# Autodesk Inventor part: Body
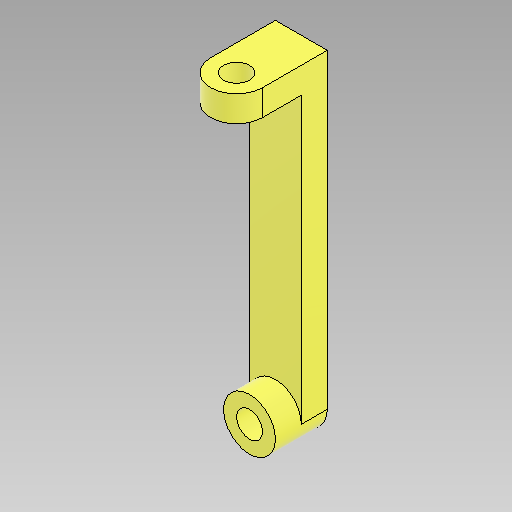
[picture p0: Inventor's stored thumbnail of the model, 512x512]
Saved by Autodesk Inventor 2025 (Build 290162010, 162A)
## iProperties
Created: 2024-10
Part Number: Body
Material: Generic
Document SubType Name: Modeling
Designer: Dennis
Mass: 31.7124 g
Surface Area: 104.562 cm^2
Volume: 31.7124 cm^3
Density: 1 g/cm^3
Appearance: Smooth - Yellow
Author: Dennis
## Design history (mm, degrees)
sketch "Sketch1"
  geometry: C1 r 10 at (0, 0); 1 further point
  constraints: 1 centre point, 1 coincident
  dimensions: "d0" = 20 diameter of C1
extrude "Extrusion1" new body sketch "Sketch1" distance "d1" = 20; taper "d2" = 0 deg
sketch "Sketch2"
  geometry: L1 (0, 0)-(120, 0); L2 (120, 0)-(120, 35); L3 (120, 35)-(110, 35); L4 (110, 35)-(110, 10); L5 (110, 10)-(0, 10); L6 (0, 10)-(0, 0)
  constraints: 12 end point, 6 perpendicular, 1 horizontal
  dimensions: "d3" = 10 distance of L5.end L1.start; "d4" = 120 distance of L1.start L1.end; "d5" = 35 distance of L1.end L2.end
extrude "Extrusion2" join sketch "Sketch2" stored distance "d6" = 20; taper "d7" = 0 deg
feature "Full Round Fillet1"
sketch "Sketch3"
  geometry: C1 r 5 at (0, 0); 1 further point
  constraints: 1 centre point, 1 coincident
  dimensions: "d8" = 10 diameter of C1
extrude "Extrusion3" cut sketch "Sketch3" stored distance "d9" = 20; taper "d10" = 0 deg
sketch "Sketch4"
  geometry: C1 r 5 at (10, -25); A1 r 10 centre (10, -25) between (0, -25) and (20, -25) reference; 1 further point
  constraints: 1 centre point, 1 coincident
  dimensions: "d11" = 10 diameter of C1
extrude "Extrusion4" cut sketch "Sketch4" stored distance "d12" = 10; taper "d13" = 0 deg
body "Solid1"
